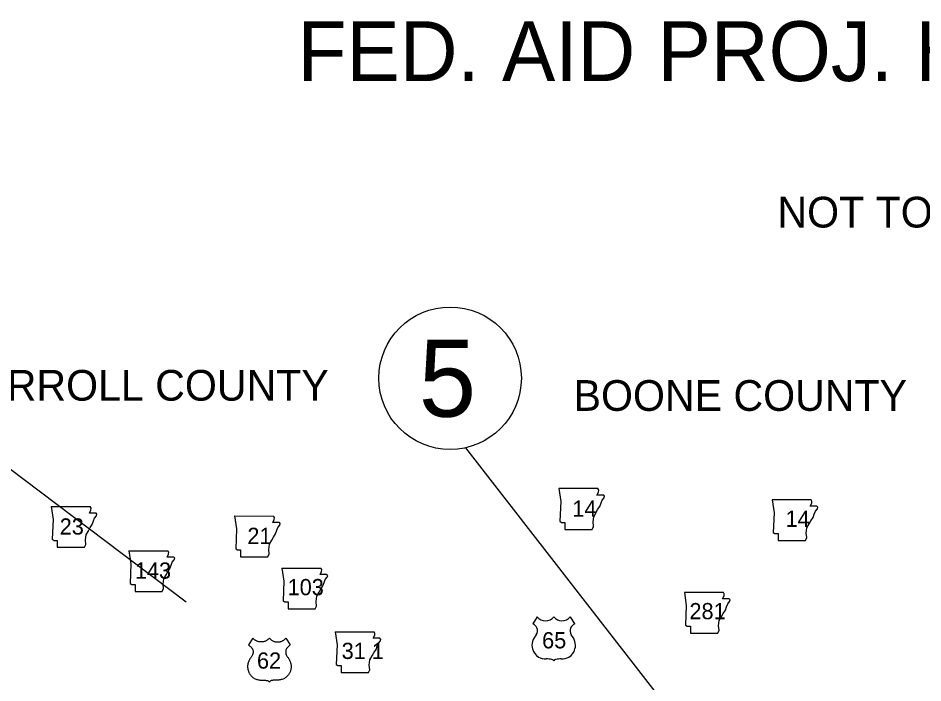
# Model space of a CAD drawing. Extents: x -819161 to 80911, y -6604 to 768454.
# Drawn here: x 41002 to 43651, y 5796 to 7744 of the extents above; entities that cross this region are included whole.
import ezdxf

# ---------------------------------------------------------------- set-up
doc = ezdxf.new("R2010")
doc.units = 0
for name, color, linetype in [('Default', 7, 'Continuous'), ('Level 21', 7, 'Continuous'), ('Level 22', 7, 'Continuous')]:
    doc.layers.add(name, color=color, linetype=linetype)

msp = doc.modelspace()

# ---------------------------------------------------------------- linework, layer by layer
at = {"layer": 'Default'}
for points in [[(40547.9, 6747.8), (41494.3, 6034.3)], [(42312.2, 6485.2), (42978.2, 5626.8)]]:
    msp.add_lwpolyline(points, dxfattribs=at)
msp.add_circle((42266.6, 6688.8), 208.7, dxfattribs=at)
at = {"layer": 'Level 21'}
for p, q in [((41098.8, 6312.8), (41104.6, 6274.7)), ((41215.6, 6308.3), (41212.9, 6312.7)), ((41214.9, 6302.6), (41215.6, 6308.3)), ((41210.5, 6293.7), (41214.9, 6302.6)), ((41230.2, 6293.7), (41210.5, 6293.7)), ((41222.6, 6270.9), (41225.7, 6279.1)), ((41225.7, 6279.1), (41231.4, 6286.1)), ((41232.7, 6290.6), (41230.2, 6293.7)), ((41231.4, 6286.1), (41232.7, 6290.6)), ((41635.6, 6285.3), (41641.3, 6247.2)), ((41752.3, 6280.8), (41749.7, 6285.2)), ((41751.7, 6275.1), (41752.3, 6280.8)), ((41104.6, 6274.7), (41102, 6217)), ((41212.4, 6251.2), (41218.7, 6260.7)), ((41218.7, 6260.7), (41222.6, 6270.9)), ((41747.2, 6266.2), (41751.7, 6275.1)), ((41766.9, 6266.2), (41747.2, 6266.2)), ((41762.5, 6251.7), (41768.2, 6258.6)), ((41769.4, 6263.1), (41766.9, 6266.2)), ((41768.2, 6258.6), (41769.4, 6263.1)), ((41199.1, 6215.1), (41201, 6230.3)), ((41201, 6230.3), (41208, 6242.3)), ((41208, 6242.3), (41212.4, 6251.2)), ((41641.3, 6247.2), (41638.8, 6189.5)), ((41749.1, 6223.7), (41755.5, 6233.3)), ((41755.5, 6233.3), (41759.3, 6243.4)), ((41759.3, 6243.4), (41762.5, 6251.7)), ((41102, 6217), (41107.1, 6213.8)), ((41107.1, 6213.8), (41116.6, 6213.8)), ((41116.6, 6213.8), (41116.6, 6193.5)), ((41196.5, 6193.5), (41200.3, 6201.7)), ((41200.3, 6201.7), (41199.1, 6215.1)), ((41735.8, 6187.6), (41737.7, 6202.8)), ((41737.7, 6202.8), (41744.7, 6214.9)), ((41744.7, 6214.9), (41749.1, 6223.7)), ((41116.6, 6193.5), (41196.5, 6193.5)), ((41326.3, 6183.6), (41332, 6145.5)), ((41438, 6164.6), (41442.4, 6173.5)), ((41443, 6179.2), (41440.4, 6183.6)), ((41442.4, 6173.5), (41443, 6179.2)), ((41638.8, 6189.5), (41643.8, 6186.3)), ((41643.8, 6186.3), (41653.3, 6186.3)), ((41653.3, 6186.3), (41653.3, 6166)), ((41733.3, 6166), (41737.1, 6174.3)), ((41737.1, 6174.3), (41735.8, 6187.6)), ((41457.6, 6164.6), (41438, 6164.6)), ((41450, 6141.7), (41453.2, 6150)), ((41453.2, 6150), (41458.9, 6157)), ((41460.2, 6161.4), (41457.6, 6164.6)), ((41458.9, 6157), (41460.2, 6161.4)), ((41653.3, 6166), (41733.3, 6166)), ((41332, 6145.5), (41329.5, 6087.8)), ((41435.4, 6113.2), (41439.9, 6122.1)), ((41439.9, 6122.1), (41446.2, 6131.6)), ((41446.2, 6131.6), (41450, 6141.7)), ((41774.3, 6132.6), (41780, 6094.6)), ((41885.9, 6113.6), (41890.4, 6122.5)), ((41891, 6128.2), (41888.4, 6132.6)), ((41890.4, 6122.5), (41891, 6128.2)), ((41426.5, 6085.9), (41428.5, 6101.1)), ((41428.5, 6101.1), (41435.4, 6113.2)), ((41780, 6094.6), (41777.5, 6036.8)), ((41905.6, 6113.6), (41885.9, 6113.6)), ((41898, 6090.8), (41901.2, 6099)), ((41901.2, 6099), (41906.9, 6106)), ((41908.2, 6110.4), (41905.6, 6113.6)), ((41906.9, 6106), (41908.2, 6110.4)), ((41329.5, 6087.8), (41334.6, 6084.6)), ((41334.6, 6084.6), (41344.1, 6084.6)), ((41344.1, 6084.6), (41344.1, 6064.3)), ((41424, 6064.3), (41427.8, 6072.6)), ((41427.8, 6072.6), (41426.5, 6085.9)), ((41883.4, 6062.2), (41887.8, 6071.1)), ((41887.8, 6071.1), (41894.2, 6080.6)), ((41894.2, 6080.6), (41898, 6090.8)), ((41344.1, 6064.3), (41424, 6064.3)), ((41874.5, 6034.9), (41876.4, 6050.2)), ((41876.4, 6050.2), (41883.4, 6062.2)), ((41777.5, 6036.8), (41782.5, 6033.7)), ((41782.5, 6033.7), (41792.1, 6033.7)), ((41792.1, 6033.7), (41792.1, 6013.4)), ((41872, 6013.4), (41875.8, 6021.6)), ((41875.8, 6021.6), (41874.5, 6034.9)), ((41792.1, 6013.4), (41872, 6013.4)), ((41929.8, 5945.9), (41935.5, 5907.9)), ((42041.4, 5926.9), (42045.9, 5935.8)), ((42046.5, 5941.5), (42043.9, 5945.9)), ((42045.9, 5935.8), (42046.5, 5941.5)), ((41935.5, 5907.9), (41932.9, 5850.2)), ((42061.1, 5926.9), (42041.4, 5926.9)), ((42053.5, 5904.1), (42056.7, 5912.3)), ((42056.7, 5912.3), (42062.4, 5919.3)), ((42063.6, 5923.7), (42061.1, 5926.9)), ((42062.4, 5919.3), (42063.6, 5923.7)), ((42038.9, 5875.5), (42043.3, 5884.4)), ((42043.3, 5884.4), (42049.7, 5893.9)), ((42049.7, 5893.9), (42053.5, 5904.1)), ((42030, 5848.2), (42031.9, 5863.5)), ((42031.9, 5863.5), (42038.9, 5875.5)), ((41932.9, 5850.2), (41938, 5847)), ((41938, 5847), (41947.5, 5847)), ((41947.5, 5847), (41947.5, 5826.7)), ((42027.5, 5826.7), (42031.3, 5834.9)), ((42031.3, 5834.9), (42030, 5848.2)), ((41947.5, 5826.7), (42027.5, 5826.7))]:
    msp.add_line(p, q, dxfattribs=at)
for points in [[(42585, 6365.5), (42590.7, 6327.4), (42588.1, 6269.7), (42593.2, 6266.5), (42602.7, 6266.5), (42602.7, 6246.2), (42682.7, 6246.2), (42686.5, 6254.5), (42685.2, 6267.8), (42687.1, 6283), (42694.1, 6295.1), (42698.5, 6304), (42704.9, 6313.5), (42708.7, 6323.6), (42711.8, 6331.9), (42717.6, 6338.9), (42718.8, 6343.3), (42716.3, 6346.5), (42696.6, 6346.5), (42701.1, 6355.4), (42701.7, 6361.1), (42699.1, 6365.4)], [(43209.3, 6333), (43215, 6294.9), (43212.4, 6237.2), (43217.5, 6234), (43227, 6234), (43227, 6213.7), (43307, 6213.7), (43310.8, 6221.9), (43309.5, 6235.3), (43311.4, 6250.5), (43318.4, 6262.5), (43322.8, 6271.4), (43329.2, 6280.9), (43333, 6291.1), (43336.2, 6299.3), (43341.9, 6306.3), (43343.1, 6310.8), (43340.6, 6313.9), (43320.9, 6313.9), (43325.4, 6322.8), (43326, 6328.5), (43323.4, 6332.9)], [(42952.6, 6061.5), (42958.3, 6023.4), (42955.7, 5965.7), (42960.8, 5962.5), (42970.3, 5962.5), (42970.3, 5942.2), (43050.3, 5942.2), (43054.1, 5950.4), (43052.8, 5963.8), (43054.7, 5979), (43061.7, 5991), (43066.1, 5999.9), (43072.5, 6009.4), (43076.3, 6019.6), (43079.4, 6027.8), (43085.1, 6034.8), (43086.4, 6039.3), (43083.9, 6042.4), (43064.2, 6042.4), (43068.7, 6051.3), (43069.3, 6057), (43066.7, 6061.4)]]:
    msp.add_lwpolyline(points, close=True, dxfattribs=at)
for points in [[(41098.8, 6312.8), (41212.9, 6312.7)], [(41635.6, 6285.3), (41749.7, 6285.2)], [(41326.3, 6183.6), (41440.4, 6183.6)], [(41774.3, 6132.6), (41888.4, 6132.6)], [(41929.8, 5945.9), (42043.9, 5945.9)]]:
    msp.add_lwpolyline(points, dxfattribs=at)
at = {"layer": 'Level 22'}
for p, q in [((42521.8, 5989.6), (42508.8, 5969.5)), ((42618.3, 5989.6), (42631.3, 5969.5))]:
    msp.add_line(p, q, dxfattribs=at)
for points in [[(41737.5, 5927.3), (41736.5, 5926.2), (41735.6, 5925.3), (41734.5, 5924.3), (41733.4, 5923.3), (41732.2, 5922.4), (41730.9, 5921.5), (41729.4, 5920.6), (41727.8, 5919.6), (41725.7, 5918.7), (41724.1, 5918), (41722.2, 5917.5), (41720.6, 5917), (41719, 5916.7), (41717.4, 5916.5), (41715.9, 5916.3), (41713.9, 5916.2), (41712.2, 5916.2), (41710.8, 5916.3), (41709.4, 5916.5), (41708, 5916.7), (41706.3, 5917), (41704.6, 5917.4), (41702.7, 5918.1), (41701, 5918.8), (41699.5, 5919.4), (41698.1, 5920.2), (41696.8, 5920.9), (41695.4, 5921.9), (41694.1, 5922.8), (41692.9, 5923.8), (41692, 5924.6), (41691, 5925.6), (41690, 5926.6), (41689.3, 5927.5), (41676.3, 5907.4), (41677.2, 5906.8), (41678.3, 5906.1), (41679.3, 5905.4), (41680.7, 5904.3), (41681.9, 5903.3), (41682.8, 5902.4), (41683.8, 5901.4), (41684.9, 5900.2), (41685.6, 5899.3), (41686.3, 5898.4), (41687.1, 5897.4), (41687.8, 5896.3), (41688.5, 5895), (41689, 5893.4), (41689.4, 5891.9), (41689.6, 5890.2), (41689.8, 5888.7), (41689.8, 5887.2), (41689.8, 5885.8), (41689.7, 5884.7), (41689.5, 5883.3), (41689.3, 5882), (41688.9, 5880.7), (41688.5, 5879.4), (41688, 5878.1), (41687.2, 5876.3), (41686.3, 5874.9), (41685.2, 5873.6), (41684, 5872), (41682.9, 5870.6), (41682, 5869.2), (41681.1, 5867.8), (41680.4, 5866.5), (41679.7, 5865.3), (41679, 5863.9), (41678.2, 5862.3), (41677.5, 5860.7), (41677, 5859.5), (41676.4, 5858), (41675.8, 5856.1), (41675.3, 5854.5), (41674.8, 5852.8), (41674.4, 5850.9), (41674.1, 5849.1), (41673.9, 5847.3), (41673.8, 5845.3), (41673.8, 5843.4), (41673.8, 5841.6), (41674.1, 5839.4), (41674.4, 5837.4), (41674.7, 5835.8), (41675.1, 5834.5), (41675.5, 5832.9), (41676.1, 5831), (41677, 5828.7), (41677.7, 5827), (41678.6, 5825.3), (41679.5, 5823.6), (41680.7, 5821.6), (41682, 5819.8), (41683.2, 5818.2), (41684.6, 5816.6), (41686.4, 5814.7), (41687.9, 5813.3), (41689.5, 5812)], [(41737.5, 5927.3), (41738.5, 5926.2), (41739.4, 5925.3), (41740.5, 5924.3), (41741.7, 5923.3), (41742.8, 5922.4), (41744.1, 5921.5), (41745.6, 5920.6), (41747.3, 5919.6), (41749.4, 5918.7), (41751, 5918), (41752.8, 5917.5), (41754.5, 5917), (41756, 5916.7), (41757.6, 5916.5), (41759.1, 5916.3), (41761.1, 5916.2), (41762.8, 5916.2), (41764.2, 5916.3), (41765.6, 5916.5), (41767, 5916.7), (41768.8, 5917), (41770.4, 5917.4), (41772.4, 5918.1), (41774, 5918.8), (41775.5, 5919.4), (41776.9, 5920.2), (41778.2, 5920.9), (41779.7, 5921.9), (41781, 5922.8), (41782.1, 5923.8), (41783.1, 5924.6), (41784, 5925.6), (41785, 5926.6), (41785.8, 5927.5), (41798.8, 5907.4), (41797.8, 5906.8), (41796.7, 5906.1), (41795.7, 5905.4), (41794.3, 5904.3), (41793.2, 5903.3), (41792.2, 5902.4), (41791.2, 5901.4), (41790.1, 5900.2), (41789.4, 5899.3), (41788.7, 5898.4), (41787.9, 5897.4), (41787.2, 5896.3), (41786.6, 5895), (41786, 5893.4), (41785.7, 5891.9), (41785.4, 5890.2), (41785.2, 5888.7), (41785.2, 5887.2), (41785.2, 5885.8), (41785.3, 5884.7), (41785.5, 5883.3), (41785.7, 5882), (41786.1, 5880.7), (41786.5, 5879.4), (41787, 5878.1), (41787.9, 5876.3), (41788.7, 5874.9), (41789.8, 5873.6), (41791, 5872), (41792.1, 5870.6), (41793, 5869.2), (41793.9, 5867.8), (41794.7, 5866.5), (41795.3, 5865.3), (41796.1, 5863.9), (41796.8, 5862.3), (41797.5, 5860.7), (41798, 5859.5), (41798.6, 5858), (41799.2, 5856.1), (41799.7, 5854.5), (41800.2, 5852.8), (41800.6, 5850.9), (41800.9, 5849.1), (41801.1, 5847.3), (41801.3, 5845.3), (41801.3, 5843.4), (41801.2, 5841.6), (41801, 5839.4), (41800.6, 5837.4), (41800.3, 5835.8), (41799.9, 5834.5), (41799.5, 5832.9), (41798.9, 5831), (41798, 5828.7), (41797.3, 5827), (41796.4, 5825.3), (41795.5, 5823.6), (41794.3, 5821.6), (41793, 5819.8), (41791.8, 5818.2), (41790.4, 5816.6), (41788.6, 5814.7), (41787.1, 5813.3), (41785.5, 5812)], [(41689.5, 5812), (41691.1, 5810.8), (41693.1, 5809.5), (41695.5, 5808.4), (41698.4, 5807.3), (41700.8, 5806.5), (41702.9, 5805.9), (41705.3, 5805.4), (41707.5, 5805), (41709.9, 5804.6), (41712.9, 5804.4), (41715.3, 5804.3), (41717.3, 5804.3), (41719.2, 5804.3), (41721.1, 5804.2), (41723, 5804.1), (41724.6, 5804), (41726.1, 5803.9), (41728.1, 5803.7), (41730.1, 5803.4), (41731.3, 5803.3), (41732.3, 5803.1), (41733.5, 5802.6), (41734.1, 5802.2), (41734.7, 5801.8), (41735.5, 5801.2), (41736.3, 5800.4), (41736.9, 5799.6), (41737.5, 5798.6)], [(41785.5, 5812), (41783.9, 5810.8), (41781.9, 5809.5), (41779.5, 5808.4), (41776.6, 5807.3), (41774.3, 5806.5), (41772.2, 5805.9), (41769.8, 5805.4), (41767.5, 5805), (41765.1, 5804.6), (41762.1, 5804.4), (41759.8, 5804.3), (41757.8, 5804.3), (41755.8, 5804.3), (41753.9, 5804.2), (41752.1, 5804.1), (41750.5, 5804), (41748.9, 5803.9), (41746.9, 5803.7), (41744.9, 5803.4), (41743.7, 5803.3), (41742.7, 5803.1), (41741.6, 5802.6), (41740.9, 5802.2), (41740.3, 5801.8), (41739.5, 5801.2), (41738.7, 5800.4), (41738.1, 5799.6), (41737.5, 5798.6)]]:
    msp.add_lwpolyline(points, dxfattribs=at)
for centre, radius, start, end in [((42546, 6009.9), 31.6, 220.075, 319.6701), ((42594.1, 6009.9), 31.6, 220.3299, 319.925), ((42491.9, 5940.4), 33.7, 30.7809, 59.9883), ((42648.3, 5940.4), 33.7, 120.0117, 149.2191), ((42559.7, 5901.9), 53.9, 138.9565, 162.6913), ((42499.3, 5949.3), 23.1, 328.8105, 21.2108), ((42640.8, 5949.3), 23.1, 158.7892, 211.1895), ((42580.4, 5901.9), 53.9, 17.3087, 41.0435), ((42541.9, 5906.3), 35.6, 160.9576, 197.3819), ((42598.2, 5906.3), 35.6, 342.6181, 19.0424), ((42547.7, 5906.4), 41.2, 195.1074, 237.1312), ((42592.4, 5906.4), 41.2, 302.8688, 344.8926), ((42548.5, 5919.4), 53, 244.0771, 269.5779), ((42549.7, 5769.4), 97, 81.1942, 90.9539), ((42561.9, 5856.4), 9.29, 28.0342, 72.9864), ((42578.3, 5856.4), 9.29, 107.0136, 151.9658), ((42590.4, 5769.4), 97, 89.0461, 98.8058), ((42591.6, 5919.4), 53, 270.4221, 295.9229)]:
    msp.add_arc(centre, radius, start, end, dxfattribs=at)

# ---------------------------------------------------------------- texts
at = {"layer": 'Default'}
for s, height, p in [('FED. AID PROJ. HSIP-0076(379)', 175.134, (41820, 7559.4)), ('NOT TO SCALE', 90, (43225.1, 7130.4)), ('5', 225.4, (42175.1, 6576.1)), ('CARROLL COUNTY', 90, (40801.3, 6623.1)), ('BOONE COUNTY', 90, (42628.2, 6593.3))]:
    msp.add_text(s, height=height, dxfattribs=at).set_placement(p)
at = {"layer": 'Level 21'}
for s, p in [('14', (42624.6, 6283.4)), ('23', (41123.6, 6230.8)), ('14', (43248.8, 6253.4)), ('21', (41673.1, 6203.4)), ('143', (41343.6, 6101.7)), ('103', (41790.9, 6053.2)), ('281', (42967.4, 5982.8)), ('31 1', (41949.1, 5866.4))]:
    msp.add_text(s, height=47.52, dxfattribs=at).set_placement(p)
at = {"layer": 'Level 22'}
for s, p in [('65', (42536, 5897.5)), ('62', (41701.2, 5838.1))]:
    msp.add_text(s, height=47.52, dxfattribs=at).set_placement(p)

doc.saveas('drawing.dxf')
